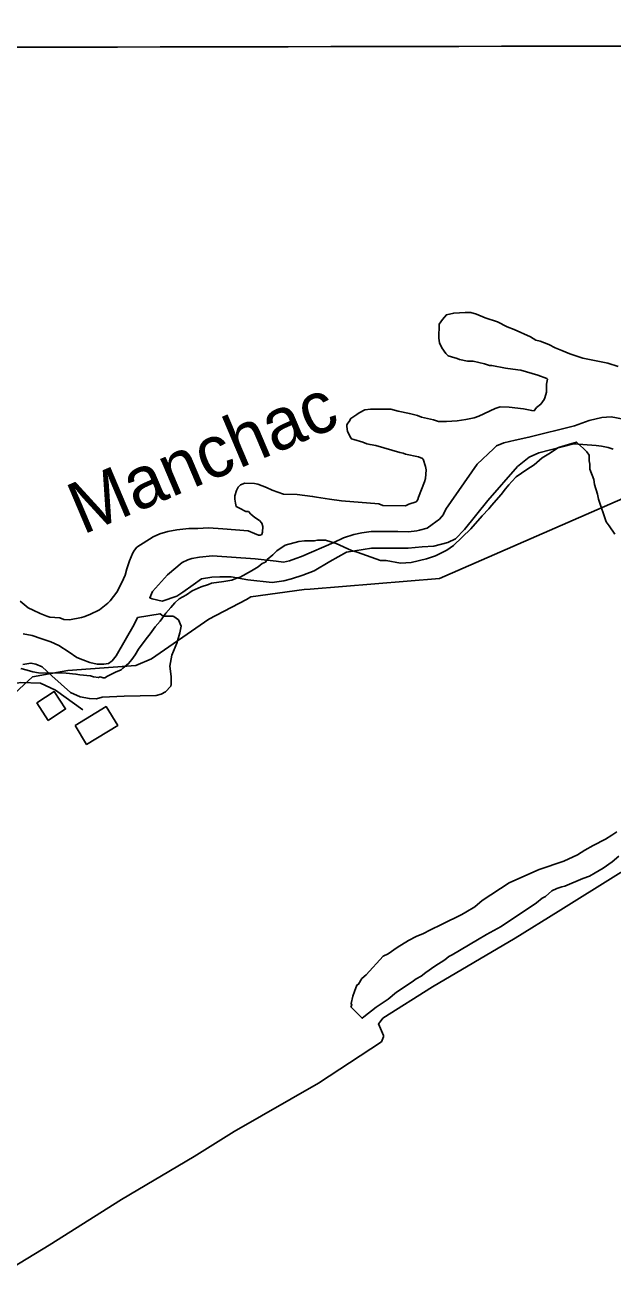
# Model space of a CAD drawing. Extents: x 3329297 to 3367176, y 649250 to 674653.
# Drawn here: x 3344336 to 3345468, y 658314 to 660753 of the extents above; entities that cross this region are included whole.
import ezdxf

# ---------------------------------------------------------------- set-up
doc = ezdxf.new("R2010")
doc.units = 0
for name, color, linetype in [('V-BLDG-OTLN', 7, 'Continuous'), ('V-GRID-MAJR', 7, 'Continuous'), ('V-RIVR-IDEN', 7, 'Continuous'), ('V-ROAD-CNTR', 7, 'Continuous'), ('V-SITE-VEGE', 7, 'Continuous'), ('V-TOPO-BNDY', 7, 'Continuous'), ('V-TOPO-SHOR', 7, 'Continuous')]:
    doc.layers.add(name, color=color, linetype=linetype)

msp = doc.modelspace()

# ---------------------------------------------------------------- linework, layer by layer
at = {"layer": 'V-BLDG-OTLN'}
for points in [[(3344380.3332018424, 659413.0981470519), (3344413.8211348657, 659434.9741032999), (3344391.946178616, 659468.4620363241), (3344358.457245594, 659446.5870800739)], [(3344432.0570983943, 659402.843167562), (3344491.901978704, 659439.576094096), (3344514.1849341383, 659403.273166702), (3344454.3400538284, 659366.5402401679)]]:
    msp.add_lwpolyline(points, close=True, dxfattribs=at)
at = {"layer": 'V-GRID-MAJR'}
msp.add_spline([(3333421.13, 660693.428), (3338679.904, 660701.46), (3343938.678, 660710.256), (3349197.451, 660719.817), (3354456.222, 660730.142), (3359714.992, 660741.233), (3364973.7600000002, 660753.089), (3364973.761, 660753.089)], degree=3, dxfattribs=at)
at = {"layer": 'V-ROAD-CNTR'}
msp.add_lwpolyline([(3344094.349290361, 659294.344366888), (3344143.864189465, 659323.424545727), (3344158.0113034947, 659343.8592659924), (3344179.23197454, 659387.0865588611), (3344202.024547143, 659427.1700486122), (3344233.4625783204, 659453.1064243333), (3344272.760117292, 659477.4708984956), (3344327.776671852, 659486.1163570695), (3344365.5023092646, 659484.5444555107), (3344394.582488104, 659471.1832922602), (3344447.114, 659433.389)], dxfattribs=at)
at = {"layer": 'V-SITE-VEGE'}
for points in [[(3345157.3910000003, 660113.925), (3345151.176, 660115.58), (3345146.568, 660120.329), (3345138.933, 660131.368), (3345134.394, 660140.799), (3345132.977, 660150.183), (3345133.381, 660176.703), (3345139.762, 660185.968), (3345147.704, 660195.208), (3345161.791, 660198.116), (3345183.6550000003, 660199.345), (3345194.575, 660199.179), (3345205.446, 660195.892), (3345222.512, 660189.394), (3345245.793, 660181.2390000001), (3345264.3710000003, 660171.595), (3345278.338, 660166.7000000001), (3345309.326, 660152.188), (3345320.15, 660145.782), (3345327.926, 660144.105), (3345344.992, 660137.604), (3345357.377, 660131.176), (3345369.785, 660126.305), (3345385.291, 660119.83), (3345410.131, 660111.65), (3345458.349, 660101.555), (3345478.534, 660095.01)], [(3344793.392, 659776.175), (3344793.556, 659787.093), (3344792.09, 659793.358), (3344787.482, 659798.109), (3344778.217, 659804.491), (3344770.512, 659810.85), (3344765.9020000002, 659815.599), (3344761.222, 659815.671), (3344748.84, 659822.1), (3344742.645, 659825.3150000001), (3344741.178, 659831.58), (3344739.739, 659839.4010000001), (3344739.8310000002, 659845.643), (3344743.1180000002, 659856.514), (3344746.335, 659862.707), (3344751.085, 659867.3150000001), (3344758.931, 659870.318), (3344777.651, 659870.033), (3344783.867, 659868.378), (3344800.933, 659861.88), (3344811.781, 659857.032), (3344833.502, 659848.902), (3344860.022, 659848.498), (3344889.613, 659844.931), (3344897.39, 659843.251), (3344922.302, 659839.753), (3344945.653, 659836.28), (3345017.341, 659830.509), (3345025.095, 659827.2710000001), (3345068.774, 659826.607), (3345075.062, 659829.632), (3345089.173, 659834.103), (3345090.756, 659835.637), (3345092.363, 659838.731), (3345093.994, 659843.389), (3345105.364, 659872.861), (3345107.019, 659879.079), (3345108.84, 659896.215), (3345107.373, 659902.4770000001), (3345102.906, 659916.588), (3345101.37, 659918.1730000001), (3345093.619, 659921.411), (3345068.7290000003, 659926.47), (3345064.0700000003, 659928.1020000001), (3345057.857, 659929.755), (3345011.2460000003, 659942.948), (3345000.3510000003, 659944.67), (3344994.1350000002, 659946.3250000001), (3344986.381, 659949.563), (3344969.293, 659954.505), (3344964.6380000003, 659956.135), (3344963.102, 659957.718), (3344957.0500000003, 659970.291), (3344955.633, 659979.677), (3344955.68, 659982.7980000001), (3344957.288, 659985.892), (3344960.454, 659988.966), (3344963.669, 659995.158), (3344974.708, 660002.7930000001), (3344979.435, 660005.8420000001), (3344990.449, 660011.916), (3345001.3910000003, 660013.309), (3345040.3910000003, 660012.7170000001), (3345054.383, 660009.385), (3345076.153, 660004.3740000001), (3345091.7060000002, 660001.017), (3345099.458, 659997.779), (3345122.786, 659992.743), (3345132.099, 659989.483), (3345147.698, 659989.245), (3345168.002, 659990.496), (3345185.2090000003, 659993.357), (3345200.856, 659996.241), (3345210.265, 659999.2170000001), (3345241.699, 660014.343), (3345251.108, 660017.321), (3345268.2660000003, 660017.063), (3345296.299, 660013.5160000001), (3345311.85, 660010.159), (3345316.531, 660010.088), (3345318.114, 660011.626), (3345321.305, 660016.256), (3345329.2, 660022.38), (3345335.582, 660031.645), (3345337.1890000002, 660034.7390000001), (3345340.474, 660045.612), (3345340.7120000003, 660061.212), (3345342.414, 660070.551), (3345340.878, 660072.132), (3345323.8140000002, 660078.632), (3345291.1950000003, 660088.4890000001), (3345284.955, 660088.583), (3345261.602, 660092.059), (3345235.154, 660097.142), (3345230.474, 660097.214), (3345221.162, 660100.476), (3345199.394, 660105.485), (3345188.474, 660105.6510000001), (3345172.921, 660109.008), (3345168.2660000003, 660110.638), (3345157.3910000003, 660113.925)], [(3345472.075, 659772.116), (3345461.39, 659787.884), (3345455.271, 659795.777), (3345440.333, 659839.694), (3345438.918, 659849.078), (3345432.958, 659867.8910000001), (3345431.541, 659877.275), (3345424.049, 659897.6730000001), (3345424.191, 659907.032), (3345422.7260000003, 659913.297), (3345422.89, 659924.2170000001), (3345418.307, 659930.527), (3345412.161, 659936.861), (3345398.31, 659949.555), (3345382.6410000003, 659945.111), (3345363.826, 659939.155), (3345344.917, 659926.959), (3345332.3170000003, 659919.349), (3345316.505, 659905.545), (3345302.322, 659896.399), (3345281.83, 659882.667), (3345273.8880000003, 659873.427), (3345267.553, 659867.28), (3345261.196, 659859.576), (3345253.23, 659848.775), (3345234.179, 659827.218), (3345229.4050000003, 659821.049), (3345216.7120000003, 659807.198), (3345194.4930000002, 659782.573), (3345161.238, 659750.309), (3345148.616, 659741.138), (3345126.61, 659730.55), (3345109.356, 659724.572), (3345079.596, 659717.219), (3345059.294, 659715.968), (3345031.286, 659721.074), (3345020.366, 659721.24), (3344975.363, 659737.525), (3344964.49, 659740.81), (3344935.04, 659753.741), (3344914.855, 659760.289), (3344899.255, 659760.524), (3344892.9930000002, 659759.06), (3344874.272, 659759.345), (3344863.329, 659757.9500000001), (3344836.691, 659750.553), (3344820.926, 659739.87), (3344813.008, 659732.188), (3344801.9450000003, 659722.993), (3344798.754, 659718.36), (3344792.464, 659715.335), (3344784.571, 659709.212), (3344771.974, 659701.603), (3344749.946, 659689.455), (3344745.242, 659687.966), (3344734.25, 659683.452), (3344718.603, 659680.568), (3344695.1580000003, 659677.804), (3344688.87, 659674.779), (3344674.758, 659670.312), (3344657.481, 659662.7710000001), (3344646.4420000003, 659655.138), (3344632.284, 659647.551), (3344624.369, 659639.871), (3344616.4250000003, 659630.628), (3344606.897, 659619.849), (3344595.742, 659604.416), (3344586.217, 659593.639), (3344576.642, 659579.741), (3344568.7, 659570.4990000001), (3344554.3540000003, 659550.432), (3344547.948, 659539.607), (3344541.566, 659530.341)], [(3344326.387, 659642.834), (3344341.798, 659630.1140000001), (3344351.086, 659625.2930000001), (3344365.0300000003, 659618.84), (3344377.4390000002, 659613.97), (3344383.657, 659612.317), (3344402.3510000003, 659610.4720000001), (3344410.105, 659607.234), (3344421.025, 659607.068), (3344444.495, 659611.3910000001), (3344449.199, 659612.882), (3344460.191, 659617.394), (3344479.053, 659626.47), (3344494.841, 659638.713), (3344499.59, 659643.323), (3344512.333, 659660.2930000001), (3344521.975, 659678.871), (3344528.428, 659692.8150000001), (3344531.738, 659705.2490000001), (3344536.6550000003, 659720.779), (3344543.131, 659736.282), (3344546.322, 659740.915), (3344551.099, 659747.083), (3344582.6040000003, 659766.89), (3344595.179, 659772.941), (3344610.85, 659777.381), (3344628.055, 659780.247), (3344651.503, 659783.009), (3344668.663, 659782.747), (3344688.967, 659784.001), (3344717.022, 659782.014), (3344765.335, 659778.162), (3344777.7430000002, 659773.292), (3344785.495, 659770.054), (3344788.614, 659770.007), (3344791.7600000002, 659771.518), (3344793.392, 659776.175)], [(3344541.566, 659530.341), (3344535.207, 659522.637), (3344524.146, 659513.443), (3344520.978, 659510.367), (3344509.988, 659505.856), (3344494.27, 659498.29), (3344489.543, 659495.245), (3344486.424, 659495.292), (3344480.2060000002, 659496.947), (3344477.062, 659495.433), (3344467.727, 659497.135), (3344461.5100000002, 659498.79), (3344441.255, 659500.658), (3344433.4790000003, 659502.335), (3344414.7830000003, 659504.18), (3344361.7430000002, 659504.985), (3344350.846, 659506.712), (3344339.973, 659509.997), (3344327.542, 659513.306)], [(3345479.812, 659150.986), (3345467.168, 659140.257), (3345449.8170000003, 659128.036), (3345434.076, 659118.9130000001), (3345423.062, 659112.838), (3345410.512, 659108.3470000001), (3345375.954, 659093.268), (3345369.691, 659091.803), (3345360.285, 659088.827), (3345350.8540000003, 659084.287), (3345338.207, 659073.556), (3345331.9220000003, 659070.533), (3345320.859, 659061.337), (3345253.0700000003, 659015.558), (3345224.752, 659000.383), (3345207.428, 658989.725), (3345158.6180000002, 658960.817), (3345152.3310000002, 658957.792), (3345144.44, 658951.671), (3345125.529, 658939.475), (3345108.178, 658927.257), (3345098.7, 658919.5970000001), (3345089.269, 658915.063), (3345081.376, 658908.939), (3345051.426, 658889.109), (3345035.615, 658875.305), (3345011.9790000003, 658860.062), (3344988.294, 658841.697), (3344985.128, 658838.623), (3344963.62, 658860.795), (3344965.228, 658863.892), (3344963.714, 658867.035), (3344967.046, 658881.027), (3344970.309, 658890.341), (3344975.179, 658902.748), (3344978.323, 658904.262), (3344984.727, 658915.087), (3344992.646, 658922.767), (3345025.951, 658958.1510000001), (3345035.382, 658962.687), (3345052.73, 658974.907), (3345074.781, 658988.617), (3345088.9390000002, 658996.205), (3345103.074, 659002.23), (3345115.649, 659008.282), (3345139.238, 659020.406), (3345176.9620000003, 659038.557), (3345184.833, 659043.118), (3345202.159, 659053.778), (3345216.386, 659066.041), (3345268.387, 659099.584), (3345304.528, 659116.199), (3345326.509, 659125.2270000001), (3345373.568, 659141.676), (3345400.278, 659153.753), (3345414.461, 659162.902), (3345430.201, 659172.023), (3345453.79, 659184.148), (3345466.3880000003, 659191.76), (3345475.843, 659197.857)]]:
    msp.add_lwpolyline(points, dxfattribs=at)
at = {"layer": 'V-TOPO-BNDY'}
for p, q in [((3345134.3000000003, 659686.77), (3345497.914, 659845.0700000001)), ((3344770.649, 659651.384), (3344873.535, 659665.2599999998)), ((3344873.535, 659665.2599999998), (3344885.028, 659666.2079999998)), ((3344885.028, 659666.2079999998), (3345134.3000000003, 659686.77)), ((3344689.555, 659608.186), (3344762.066, 659645.84)), ((3344762.066, 659645.84), (3344770.649, 659651.384)), ((3344579.382, 659531.837), (3344689.555, 659608.186)), ((3344418.162, 659509.169), (3344549.25, 659518.606)), ((3344549.25, 659518.606), (3344579.382, 659531.8370000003)), ((3344275.5700000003, 659428.2589999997), (3344350.275, 659496.6809999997)), ((3344350.275, 659496.681), (3344407.453, 659507.459)), ((3344407.453, 659507.459), (3344418.162, 659509.169))]:
    msp.add_line(p, q, dxfattribs=at)
at = {"layer": 'V-TOPO-SHOR'}
for points in [[(3344580.896, 659661.809), (3344609.873, 659693.925), (3344638.123, 659717.123), (3344649.129, 659722.563), (3344656.6920000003, 659725.27), (3344671.802, 659727.9450000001), (3344696.522, 659730.5700000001), (3344778.849, 659724.686), (3344819.318, 659719.689), (3344833.723, 659718.248), (3344845.401, 659720.937), (3344857.089, 659725), (3344868.089, 659729.063), (3344930.6720000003, 659756.215), (3344949.245, 659765.0480000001), (3344969.176, 659771.131), (3344984.29, 659774.49), (3345002.833, 659777.148), (3345053.617, 659776.904), (3345074.208, 659776.806), (3345090.686, 659778.784), (3345095.495, 659779.4500000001), (3345110.611, 659783.495), (3345120.255, 659790.997), (3345134.032, 659801.226), (3345141.6240000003, 659810.111), (3345141.626, 659810.799), (3345146.4760000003, 659820.383), (3345206.599, 659907.255), (3345238.31, 659936.613), (3345243.825, 659942.078), (3345258.268, 659948.185), (3345280.255, 659953.571), (3345306.361, 659958.937), (3345394.312, 659981.164), (3345422.4990000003, 659991.324), (3345447.231, 659996.696), (3345465.0810000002, 659997.982), (3345489.0810000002, 659993.751)], [(3344580.896, 659661.809), (3344576.032, 659649.478), (3344580.826, 659647.397), (3344600.022, 659643.186), (3344628.207, 659652.66), (3344639.909, 659660.154), (3344659.879, 659674.469), (3344675.72, 659686.061), (3344695.639, 659689.397), (3344710.739, 659690.012), (3344732.702, 659689.905), (3344764.929, 659684.263), (3344811.572, 659678.547), (3344834.235, 659681.871), (3344849.3540000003, 659685.916), (3344870.661, 659692.676), (3344892.665, 659701.495), (3344922.947, 659719.194), (3344955.291, 659737.568), (3345003.365, 659744.89), (3345074.054, 659745.236), (3345100.8340000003, 659747.853), (3345123.487, 659749.117), (3345150.285, 659755.853), (3345164.734, 659763.332), (3345182.662, 659781.09), (3345227.54, 659837.152), (3345284.816, 659902.762), (3345306.863, 659920.502), (3345325.432, 659928.649), (3345392.772, 659946.169), (3345435.995, 659943.218), (3345446.282, 659941.797), (3345459.308, 659938.987), (3345468.9020000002, 659936.198)], [(3344473.5270000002, 659454.373), (3344484.525, 659457.752), (3344526.397, 659459.612), (3344588.168, 659460.689), (3344597.79, 659463.386), (3344606.049, 659468.152), (3344616.396, 659479.082), (3344617.098, 659482.51), (3344617.17, 659497.608), (3344614.52, 659517.525), (3344618.741, 659538.779), (3344627.773, 659562.071), (3344634.046, 659581.943), (3344636.165, 659594.9720000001), (3344631.418, 659606.662), (3344622.5300000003, 659613.568), (3344620.473, 659614.264), (3344601.941, 659613.666), (3344595.787, 659618.5), (3344552.515, 659611.158)], [(3344332.066, 659579.956), (3344349.2060000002, 659576.442), (3344366.335, 659570.8690000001), (3344385.523, 659564.6020000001), (3344400.588, 659557.6680000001), (3344420.427, 659544.532), (3344435.4760000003, 659534.165), (3344447.123, 659529.991), (3344460.1380000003, 659524.439), (3344474.535, 659521.625), (3344487.575, 659521.564), (3344496.504, 659522.893), (3344503.389, 659527.665), (3344510.983, 659537.235), (3344545.59, 659598.1510000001), (3344552.515, 659611.158)], [(3344331.095, 659520.937), (3344346.893, 659523.608), (3344356.492, 659521.502), (3344368.819, 659515.954), (3344387.2660000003, 659498.708), (3344423.489, 659466.964), (3344441.98, 659458.6410000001), (3344459.806, 659455.125), (3344473.5270000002, 659454.373)], [(3344236.789, 658313.508), (3344382.019, 658401.345), (3344521.756, 658489.21), (3344661.472, 658572.269), (3344738.5670000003, 658620.628), (3344900.98, 658713.8740000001), (3345002.182, 658779.96), (3345022.15, 658793.5920000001), (3345026.313, 658803.179), (3345026.324, 658805.2390000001), (3345016.825, 658827.931), (3345019.588, 658832.037), (3345025.111, 658838.871), (3345120.798, 658899.4940000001), (3345279.782, 658993.444), (3345363.068, 659044.519), (3345479.398, 659117.395), (3345630.115, 659204.519), (3345787.7490000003, 659303.28), (3345916.4420000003, 659377.471), (3346005.909, 659429.201), (3346043.065, 659449.611), (3346074.762, 659476.225)]]:
    msp.add_lwpolyline(points, dxfattribs=at)

# ---------------------------------------------------------------- texts
at = {"layer": 'V-RIVR-IDEN'}
msp.add_text('Manchac', height=99.99980199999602, rotation=22.955863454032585, dxfattribs=at).set_placement((3344446.5153759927, 659770.310443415))

doc.saveas('drawing.dxf')
